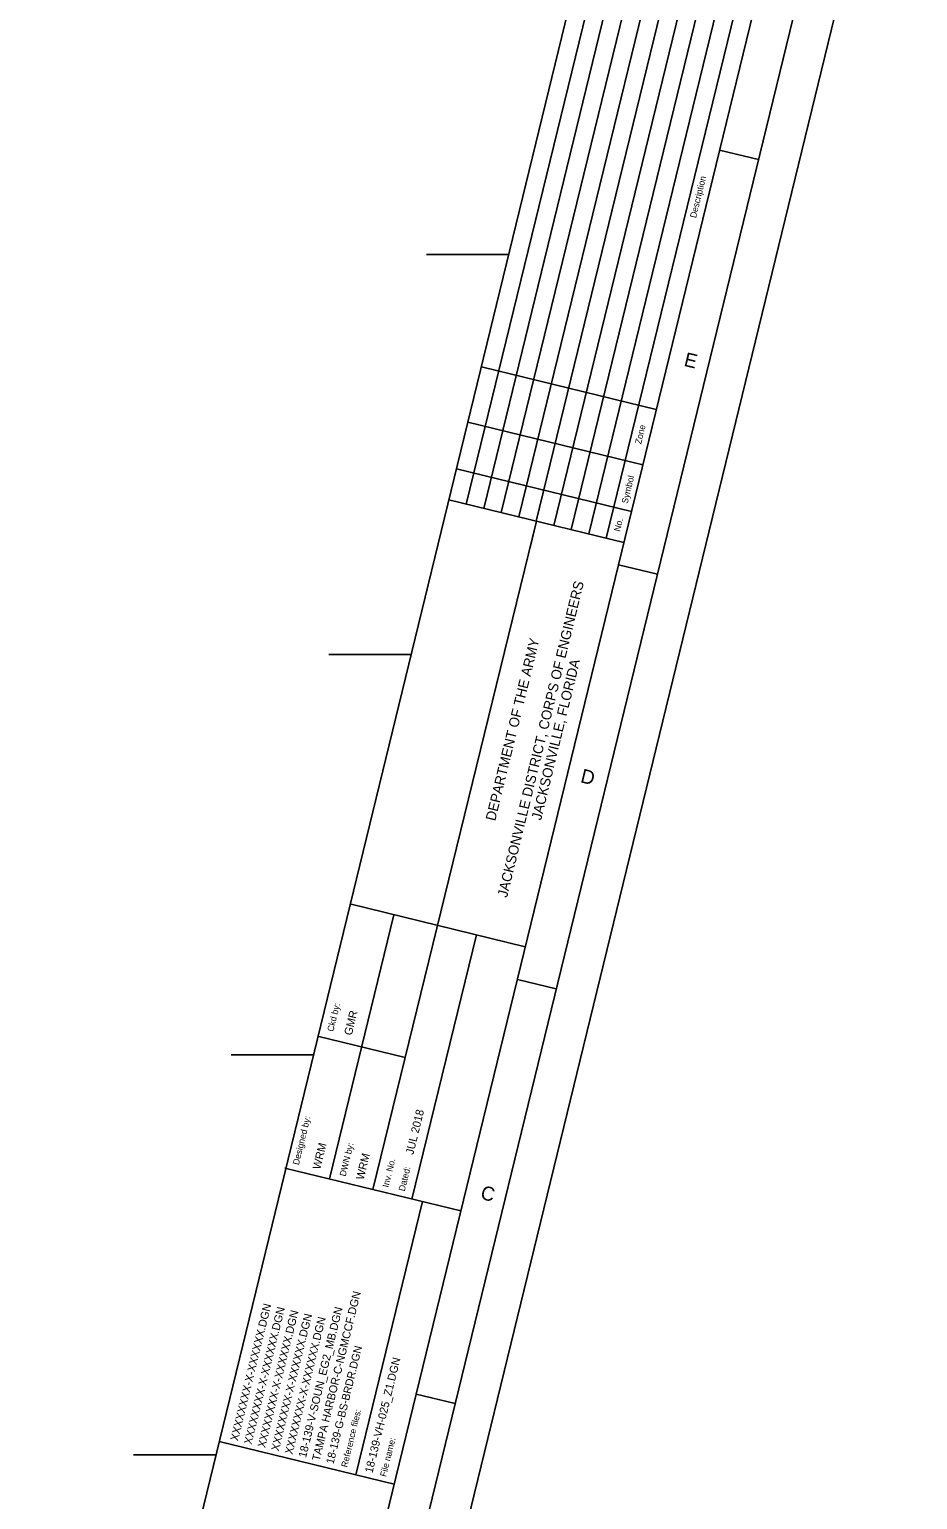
# Model space of a CAD drawing. Extents: x 403671 to 408751, y 1189919 to 1194265.
# Drawn here: x 407642 to 408751, y 1190944 to 1192781 of the extents above; entities that cross this region are included whole.
import ezdxf

# ---------------------------------------------------------------- set-up
doc = ezdxf.new("R2010")
doc.units = 0
for name, color, linetype in [('G-ANNO-NPLT', 7, 'Continuous'), ('G-ANNO-TEXT-DRWG', 7, 'Continuous'), ('G-ANNO-TEXT-PROJ', 7, 'Continuous'), ('G-ANNO-TEXT-TTLB', 7, 'Continuous'), ('G-ANNO-TTLB', 7, 'Continuous'), ('V-TOPO-COOR-STAT', 7, 'Continuous')]:
    doc.layers.add(name, color=color, linetype=linetype)

msp = doc.modelspace()

# ---------------------------------------------------------------- linework, layer by layer
at = {"layer": 'G-ANNO-NPLT'}
msp.add_lwpolyline([(404476.5, 1194264.7), (408751.2, 1193222.2), (407945.6, 1189919), (403670.9, 1190961.5)], close=True, dxfattribs=at)
at = {"layer": 'G-ANNO-TTLB'}
for p, q in [((408411.7, 1193202), (407653.5, 1190093.2)), ((408385.9, 1193002.1), (408187.4, 1192188)), ((408407.8, 1192996.8), (408209.3, 1192182.7)), ((408429.6, 1192991.4), (408231.1, 1192177.4)), ((408451.5, 1192986.1), (408253, 1192172)), ((408473.4, 1192980.8), (408274.8, 1192166.7)), ((408495.2, 1192975.4), (408296.7, 1192161.4)), ((408517.1, 1192970.1), (408318.5, 1192156.1)), ((408538.9, 1192964.8), (408340.4, 1192150.7)), ((408560.8, 1192959.4), (408362.3, 1192145.4)), ((408552.5, 1192618.6), (408503.9, 1192630.4)), ((408206.2, 1192359.5), (408424.8, 1192306.2)), ((408189.4, 1192290.3), (408408, 1192237)), ((408175.2, 1192232), (408393.7, 1192178.7)), ((408165.7, 1192193.3), (408384.3, 1192140)), ((408070.7, 1191331.7), (408275, 1192166.7)), ((408275, 1192166.7), (408266.6, 1192132.3)), ((408426.1, 1192100.4), (408377.6, 1192112.3)), ((408016.4, 1191345), (408097.1, 1191674.9)), ((408041.8, 1191688.4), (408261.1, 1191634.9)), ((408200, 1191649.8), (408119.5, 1191319.8)), ((408299.8, 1191582.3), (408251.2, 1191594.2)), ((408001.5, 1191523.4), (408111.1, 1191496.7)), ((407960.9, 1191358.5), (408180.7, 1191304.9)), ((408132.8, 1191316.6), (408049.5, 1190975.2)), ((408173.4, 1191064.2), (408124.8, 1191076.1)), ((407878.8, 1191016.8), (408097.4, 1190963.5))]:
    msp.add_line(p, q, dxfattribs=at)
for points in [[(403731.3, 1190998.2), (407908.9, 1189979.4), (408690.7, 1193185.4), (404513.2, 1194204.2)], [(408630.3, 1193148.7), (404622.8, 1194126), (403864.6, 1191017.2), (407872.1, 1190039.9)]]:
    msp.add_lwpolyline(points, close=True, dxfattribs=at)
at = {"layer": 'V-TOPO-COOR-STAT'}
for p, q in [((408137.6, 1192500), (408240.5, 1192500)), ((408015.6, 1192000), (408118.5, 1192000)), ((407893.7, 1191500), (407996.6, 1191500)), ((407771.7, 1191000), (407874.7, 1191000))]:
    msp.add_line(p, q, dxfattribs=at)

# ---------------------------------------------------------------- texts
at = {"layer": 'G-ANNO-TEXT-DRWG'}
for s, p in [('GMR', (408044.3, 1191523.6)), ('WRM', (408005, 1191356.1)), ('WRM', (408059.1, 1191343.1)), ('TAMPA HARBOR-C-NGMCCF.DGN', (408004.2, 1190991.8)), ('XXXXXXXX-X-XXXXXX.DGN', (407902.2, 1191016.7)), ('XXXXXXXX-X-XXXXXX.DGN', (407919.2, 1191012.5)), ('XXXXXXXX-X-XXXXXX.DGN', (407936.2, 1191008.4)), ('18-139-V-SOUN_EG2_MB.DGN', (407987.2, 1190995.9)), ('XXXXXXXX-X-XXXXXX.DGN', (407953.2, 1191004.2)), ('XXXXXXXX-X-XXXXXX.DGN', (407970.2, 1191000.1)), ('18-139-VH-025_Z1.DGN', (408070.2, 1190976.8))]:
    msp.add_text(s, height=10, rotation=76.2946, dxfattribs=at).set_placement(p)
at = {"layer": 'G-ANNO-TEXT-PROJ'}
for s, height, p in [('JUL 2018', 10, (408121.2, 1191374.6)), ('18-139-G-BS-BRDR.DGN', 9.8, (408021.5, 1190988))]:
    msp.add_text(s, height=height, rotation=76.2946, dxfattribs=at).set_placement(p)
at = {"layer": 'G-ANNO-TEXT-TTLB'}
for s, height, p in [('Description', 8, (408474.4, 1192544.9)), ('Zone', 8, (408405.8, 1192262.4)), ('Symbol', 8, (408388.9, 1192188)), ('No.', 8, (408379.4, 1192153.1)), ('JACKSONVILLE DISTRICT, CORPS OF ENGINEERS', 12.5, (408238.3, 1191695.8)), ('DEPARTMENT OF THE ARMY', 12.5, (408223.5, 1191791.4)), ('JACKSONVILLE, FLORIDA', 12.5, (408280.8, 1191792.3)), ('Ckd by:', 8, (408021.3, 1191528.3)), ('Designed by:', 8, (407978.2, 1191361.8)), ('DWN by:', 8, (408036.7, 1191347.5)), ('Inv. No.', 8, (408090.2, 1191333.7)), ('Dated:', 8, (408110.4, 1191328.9)), ('Reference files:', 8, (408038.7, 1190983.9)), ('File name:', 8, (408087.3, 1190972.2))]:
    msp.add_text(s, height=height, rotation=76.2946, dxfattribs=at).set_placement(p)
at = {"layer": 'G-ANNO-TTLB'}
for s, p in [('E', (408458.3, 1192360.9)), ('D', (408329.1, 1191840.6)), ('C', (408204.2, 1191320.1))]:
    msp.add_text(s, height=17.5, rotation=346.2946, dxfattribs=at).set_placement(p)

doc.saveas('drawing.dxf')
